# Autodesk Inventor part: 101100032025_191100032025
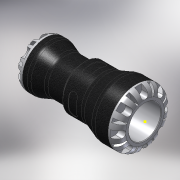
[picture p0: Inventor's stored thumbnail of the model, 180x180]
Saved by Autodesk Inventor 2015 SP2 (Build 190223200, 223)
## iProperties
Created: 2016-12
Part Number: 101100032025_191100032025
Material: PVC-Piping
Description: PLASSON REDUCING COUPLING 32X25 SERIES 1
Document SubType Name: Modeling
Designer: KIM
Mass: 164.465 g
Surface Area: 319.477 cm^2
Volume: 117.475 cm^3
Density: 1.4 g/cm^3
Appearance: Black Cast
Author: KIM
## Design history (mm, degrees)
derived "1011.ipt"
feature "Solid1::1011.ipt"
tag "TaggingFeature1"
body "Solid1"
other parameters: "d2" = 22.68, "d3" = 32, "d4" = 58, "d5" = 38.4, "d6" = 54, "d7" = 2.66667, "d8" = 47, "d9" = 25, "d10" = 31.25, "d11" = 20.16, "d12" = 48, "d13" = 2.08333, "d14" = 46.4, "d15" = 37.6, "d16" = 20 deg, "d17" = 20 deg, "d18" = 130 deg, "d22" = 7.84, "d25" = 7.84, "d26" = 0, "d28" = 360 deg, "d30" = 8 deg, "d31" = 0.64, "d32" = 8 deg, "d33" = 0.64, "d35" = 0, "d37" = 360 deg, "d39" = 6.3, "d42" = 6.3, "d43" = 0, "d45" = 360 deg, "d47" = 0.5, "d48" = 8 deg, "d49" = 8 deg, "d50" = 0.5, "d52" = 0, "d54" = 360 deg, "d56" = 9.4, "d57" = 11.6, "d58" = 0.5, "d60" = 6.96, "d61" = 8, "d62" = 12.96, "d63" = 0, "d66" = 0, "d68" = 360 deg, "d75" = 6.70702, "d77" = 45.24, "d78" = 0.58, "d_" = 32, "d1" = 25, "E_" = 58, "l_" = 54, "E1" = 47, "l1" = 48, "Plasson" = 1, "d20" = 7.875, "d21" = 9.8, "d23" = 58, "d24" = 38.4, "d40" = 47, "d41" = 31.25, "d59" = 13.41405
